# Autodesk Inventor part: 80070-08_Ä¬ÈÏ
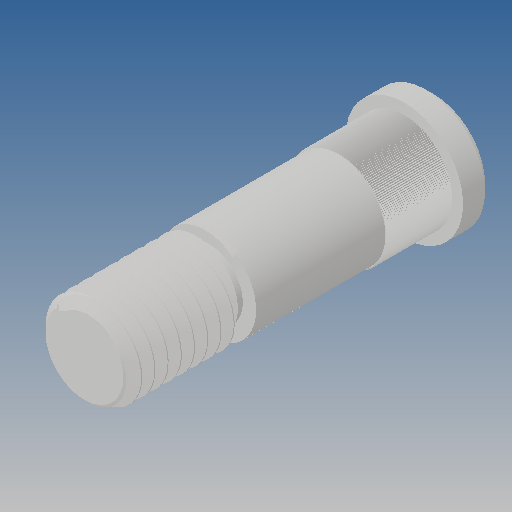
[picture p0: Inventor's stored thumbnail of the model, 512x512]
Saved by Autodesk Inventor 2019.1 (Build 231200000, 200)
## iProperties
Created: 2010-06
Part Number: 80070-08_Ä¬ÈÏ
Material: Ogólny
Document SubType Name: Modeling
Designer: CADENGINEERING4
Density: 1 g/cm^3
Appearance: Domyślna
Author: CADENGINEERING4
Revision Number: ÈÎºÎ
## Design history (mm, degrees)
feature "NONE"
node "Bryła1"
